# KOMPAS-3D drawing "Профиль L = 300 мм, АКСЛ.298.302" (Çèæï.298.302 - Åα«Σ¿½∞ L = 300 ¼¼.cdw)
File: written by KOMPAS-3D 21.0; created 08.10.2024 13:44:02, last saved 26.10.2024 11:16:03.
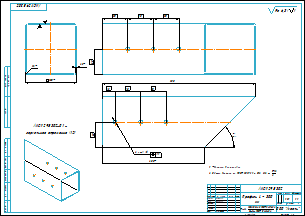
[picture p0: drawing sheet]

Sheet 1: A2, landscape

Document properties: Полное имя файла: Профиль L = 300 мм (1).m3d; Автор: Алексей Бочаров; Знак неуказанной шероховатости: 4; Параметр неуказанной шероховатости: Ra 6,3; Масса: 1.514806

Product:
- Part/product: Профиль L = 300 мм  | designation АКСЛ.298.302
    Масса: 1.514806
    Форматы листов документа: A2

Title block, sheet 1: Наименование: Профиль L = 300 / мм; designation: АКСЛ.298.302; Материал: Труба  100х100х2,5 ГОСТ 8639-82 Ст3сп ГОСТ 13663-86; Масса: 1,51; Количество листов документа: 1; organisation: ООО "Аксель"; Форматы листов документа: A2; stored path: C:\Users\Алексей Бочаров\YandexDisk\Соединения бруса\Соединения бруса\ТРИО\АКСЛ.298.302 - Профиль L = 300 мм.cdw; Разработал: Бочаров; Проверил: Захаров; Утвердил: Гелетей

Views: Вид 1, Справа, Проекционный вид 2, Проекционный вид 3, Вид 4, Изометрия
Referenced files in C:\Users\Алексей Бочаров\Desktop\Соединения бруса\ТРИО\: Профиль L = 300 мм (1).m3d
Referenced files in C:\Users\79253\YandexDisk\Соединения бруса\Соединения бруса\ТРИО\: Профиль L = 300 мм (2).m3d, Профиль L = 300 мм (1).m3d
Referenced files in C:\Users\Алексей Бочаров\YandexDisk\Соединения бруса\Соединения бруса\ТРИО\: Профиль L = 300 мм (2).m3d
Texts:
  АКСЛ.298.302-01 -
  зеркальное отражение  (1:2)
  АКСЛ.298.302 - 01
  Ra 6,3
  Ra 6,3 ( )
  АКСЛ.298.300
  АКСЛ.298.302-01 Профиль L = 300 мм
  АКСЛ.298.302 Профиль L = 300 мм
Dimensions and other numbers on the sheet: 50; 200; 300; 6 отв.; 8; 25; 100; 2,5; 2; 1:1; 1; 1,51; 01

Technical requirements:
  *Размеры для справок.
  Общие допуски по ГОСТ 30893.1 - H12, h12,    IT12 2 .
